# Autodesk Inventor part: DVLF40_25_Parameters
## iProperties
Created: 2010-03
Part Number: DVLF40_25_Parameters
Document SubType Name: Modeling
Designer: TB
Density: 1 g/cm^3
Slaglengde: 100.000 mm
Vinkel_Plussport: 0.00 deg
Vinkel_Minusport: 0.00 deg
Forlengelse_rør: 0.000 mm
Author: TB
